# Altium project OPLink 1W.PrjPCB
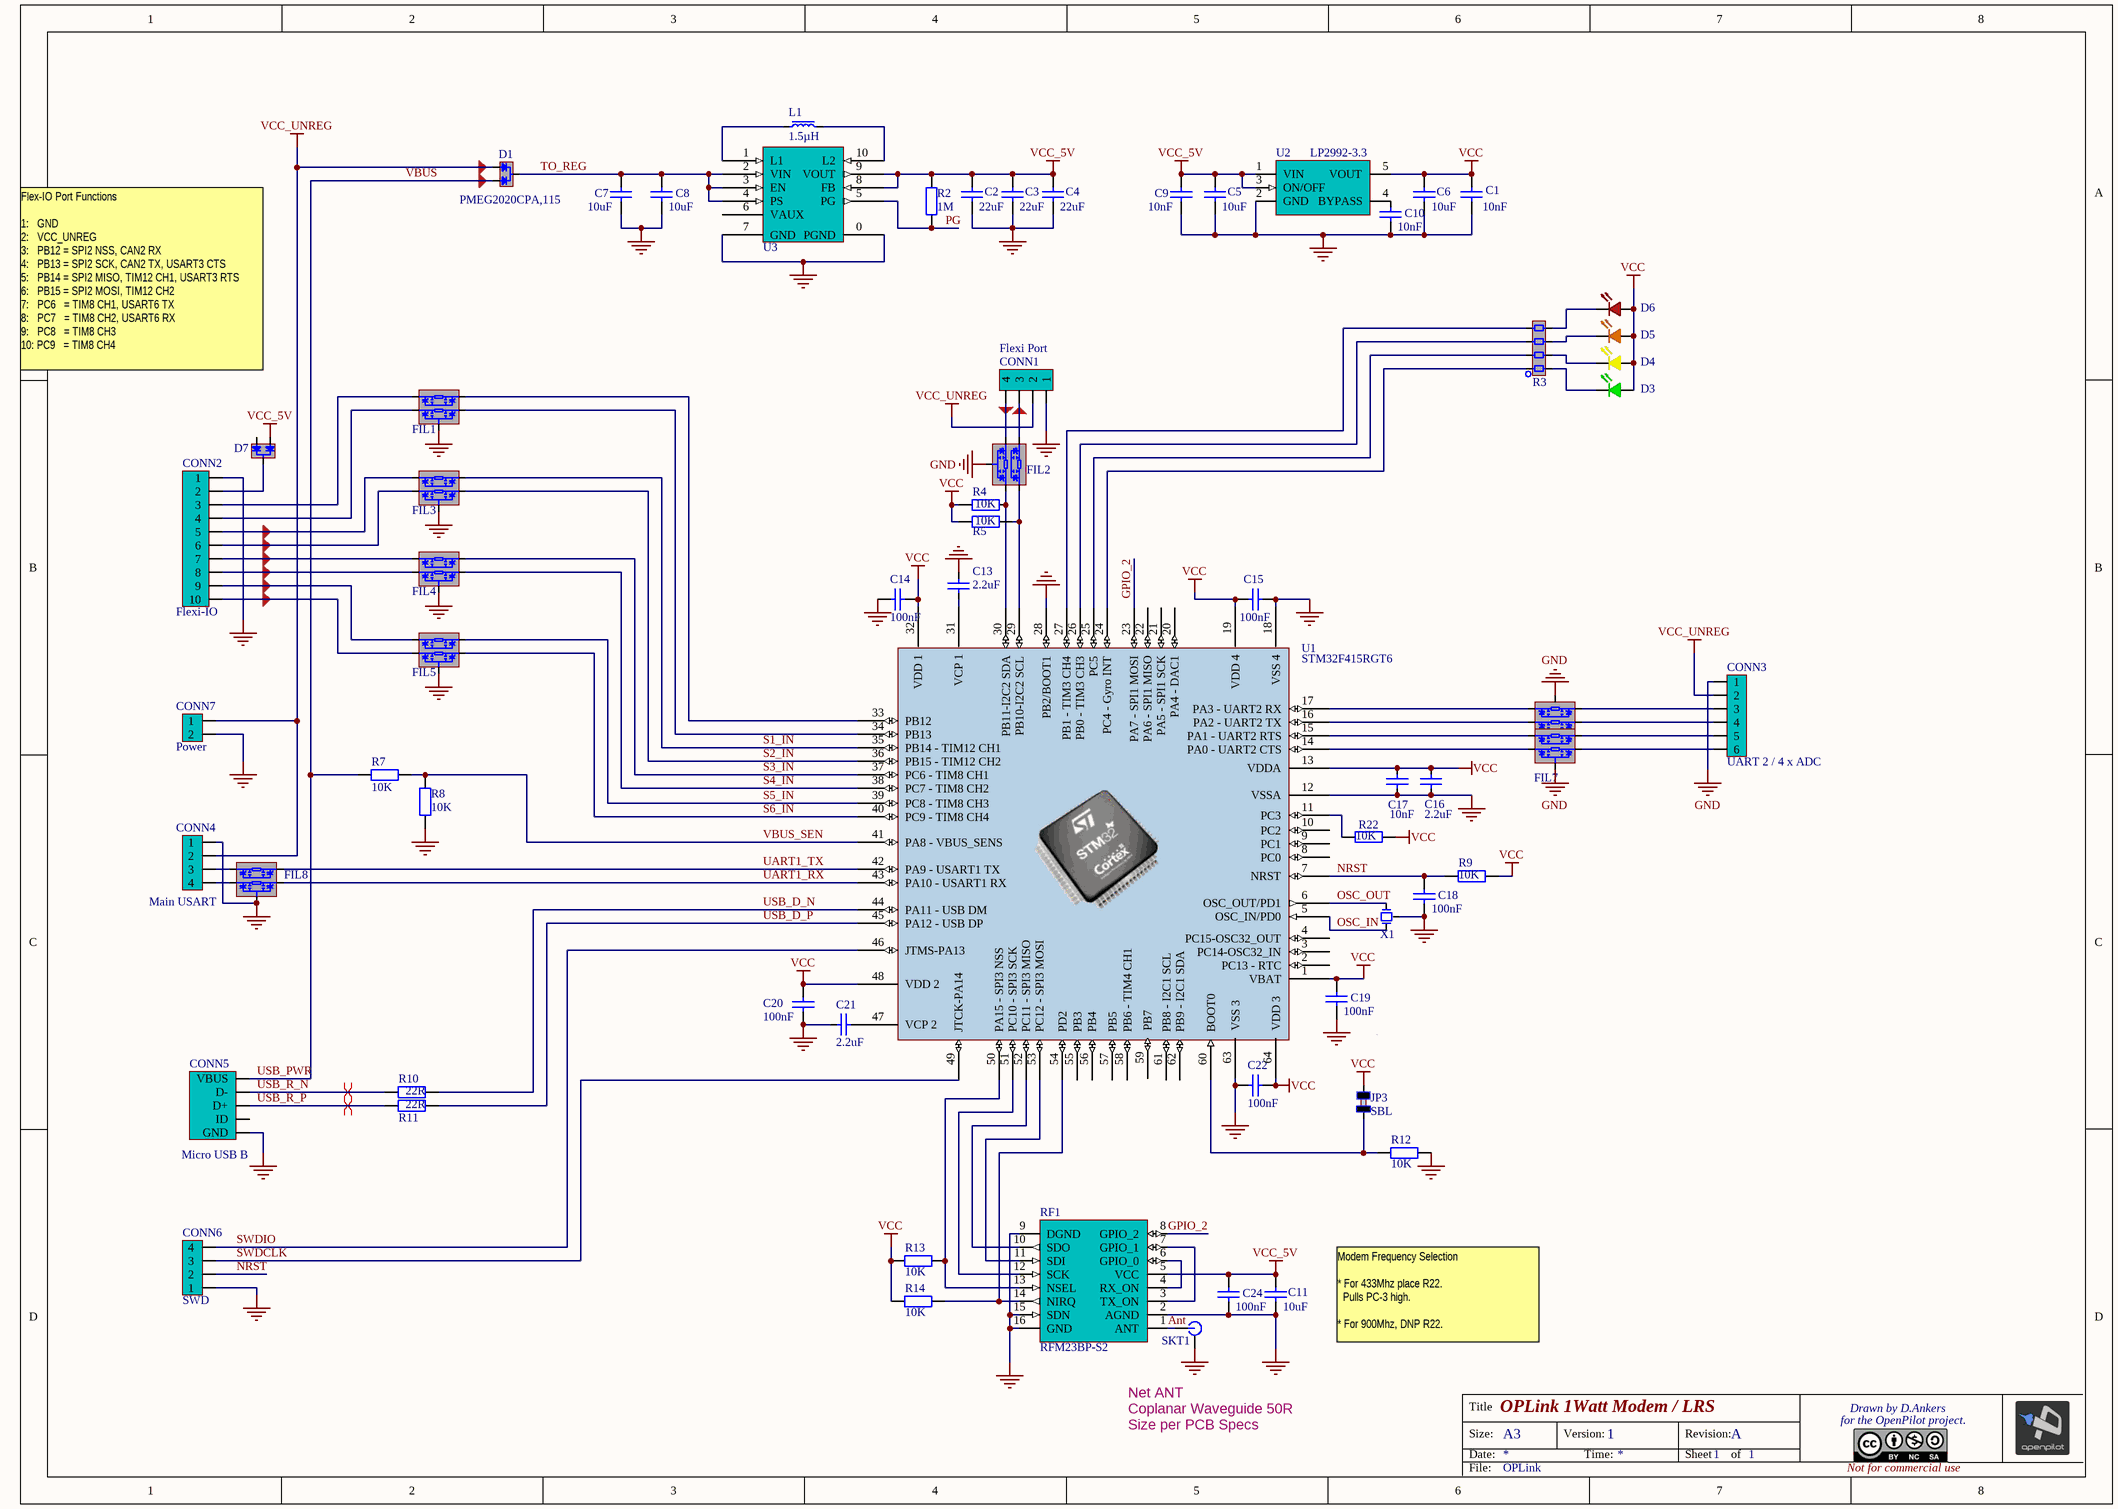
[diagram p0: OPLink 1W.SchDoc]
1 sheet, 64 parts. Net scope: global (net labels, ports and power ports of the same name join across sheets).
Board file: OPLink 1W.PcbDoc

## Sheet OPLink 1W.SchDoc: OPLink 1Watt Modem / LRS
size A3; Author: D. Ankers; CompanyName: The OpenPilot Project; DrawnBy: D. Ankers; Engineer: D. Ankers; Organization: The OpenPilot Project; DocumentNumber: 1; Revision: A; SheetNumber: 1; SheetTotal: 1

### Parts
C1  value 10nF  [CAP402N]  (hidden comment: 10n)
C2  value 22uF  [CAP805L]  (hidden comment: Cap805)
C3  value 22uF  [CAP805L]  (hidden comment: Cap805)
C4  value 22uF  [CAP805L]  (hidden comment: Cap805)
C5  value 10uF  [CAP805L]  (hidden comment: Cap805)
C6  value 10uF  [CAP805L]  (hidden comment: Cap805)
C7  value 10uF  [CAP805L]  (hidden comment: Cap805)
C8  value 10uF  [CAP805L]  (hidden comment: Cap805)
C9  value 10nF  [CAP402N]  (hidden comment: 10n)
C10  value 10nF  [CAP402N]  (hidden comment: 10n)
C11  value 10uF  [CAP805L]  (hidden comment: Cap805)
C13  value 2.2uF  [CAP603L]  (hidden comment: Cap603)
C14  value 100nF  [CAP402N]  (hidden comment: Cap402)
C15  value 100nF  [CAP402N]  (hidden comment: Cap402)
C16  value 2.2uF  [CAP603L]  (hidden comment: Cap603)
C17  value 10nF  (hidden comment: 10n)
C18  value 100nF  [CAP402N]  (hidden comment: Cap402)
C19  value 100nF  [CAP402N]  (hidden comment: Cap402)
C20  value 100nF  [CAP402N]  (hidden comment: Cap402)
C21  value 2.2uF  [CAP603L]  (hidden comment: Cap603)
C22  value 100nF  [CAP402N]  (hidden comment: Cap402)
C24  value 100nF  [CAP402N]  (hidden comment: Cap402)
CONN1  Flexi Port  [JST SH 4 Pin Side Entry]
CONN2  Flexi-IO  [JST SH 10 PIN SIDE ENTRY]
CONN3  UART 2 / 4 x ADC  [JST SH 6 Pin Side Entry]
CONN4  Main USART  [JST SH 4 Pin Side Entry]
CONN5  Micro USB B  [Micro_USB]
CONN6  SWD  [JST SH 4 Pin Side Entry]
CONN7  Power  [JST ZH 2 PIN TOP ENTRY]
D1  PMEG2020CPA,115  [3-HUSON]
D3  Green  [LED603N]  (value not drawn)
D4  Yellow  [LED603N]  (value not drawn)
D5  Orange  [LED603N]  (value not drawn)
D6  Red  [LED603N]  (value not drawn)
D7  PMEG2020CPA,115  [3-HUSON]  (value not drawn)
FIL1  IP4256CZ5-W,115  [SOT-665]  (value not drawn)
FIL2  IP4256CZ5-W,115  [SOT-665]  (value not drawn)
FIL3  IP4256CZ5-W,115  [SOT-665]  (value not drawn)
FIL4  IP4256CZ5-W,115  [SOT-665]  (value not drawn)
FIL5  IP4256CZ5-W,115  [SOT-665]  (value not drawn)
FIL6  IP4256CZ5-W,115  [SOT-665]  (value not drawn)
FIL7  IP4256CZ5-W,115  [SOT-665]  (value not drawn)
FIL8  IP4256CZ5-W,115  [SOT-665]  (value not drawn)
JP3  SBL  [TOUCH JMP 2PAD]
L1  1.5µH  [IND-ASPI-3012S]
R2  value 1M  [RES402N]  (hidden comment: Res402)
R3  Res Array 330R 1206  [TC164]  (value not drawn)
R4  value 10K  [RES402N]  (hidden comment: Res402)
R5  value 10K  [RES402N]  (hidden comment: Res402)
R7  value 10K  [RES402N]  (hidden comment: Res402)
R8  value 10K  [RES402N]  (hidden comment: Res402)
R9  value 10K  [RES402N]  (hidden comment: Res402)
R10  value 22R  [RES402N]  (hidden comment: Res402)
R11  value 22R  [RES402N]  (hidden comment: Res402)
R12  value 10K  [RES402N]  (hidden comment: Res402)
R13  value 10K  [RES402N]  (hidden comment: Res402)
R14  value 10K  [RES402N]  (hidden comment: Res402)
R22  value 10K  [RES402N]  (hidden comment: Res402)
RF1  RFM23BP-S2  [RFM23BP-S2]
SKT1  MMCX Thru hole  [MMCX_SOCKET]  (value not drawn)
U1  STM32F415RGT6  [STM32 64 Lead]
U2  LP2992-3.3  [SOT23-5L]
U3  TPS63061  [SON-10]  (value not drawn)
X1  8Mhz Ceralock  [CERALOCK 8Mhz]  (value not drawn)

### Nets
GND: C1.2 C2.2 C3.2 C4.2 C5.2 C6.2 C7.2 C8.2 C9.2 C10.2 C11.2 C13.1 C14.2 C15.1 C16.1 C17.2 C18.1 C19.1 C20.2 C21.1 C22.2 C24.1 CONN1.1 CONN2.1 CONN3.1 CONN4.1 CONN5.5(GND) CONN6.1 CONN7.2 FIL1.2(PAD) FIL2.2(PAD) FIL3.2(PAD) FIL4.2(PAD) FIL5.2(PAD) FIL6.2(PAD) FIL7.2(PAD) FIL8.2(PAD) R8.1 R12.2 RF1.2(AGND) RF1.9(N.C) RF1.15(SDN) RF1.16(GND) SKT1.2(GND) U1.12(VSSA) U1.18(VSS_4) U1.28(PB2/BOOT1) U1.63(VSS_3) U2.2(GND) U3.0(PGND) U3.7(GND) X1.3
VCC: C1.1 C6.1 C14.1 C15.2 C16.2 C17.1 C19.2 C20.1 C22.1 D3.2(A) D4.2(A) D5.2(A) D6.2(A) JP3.2 R4.2 R5.2 R9.2 R13.2 R14.2 R22.1 U1.1(VBAT) U1.13(VDDA) U1.19(VDD_4) U1.32(VDD_1) U1.48(VDD_2) U1.64(VDD_3) U2.5(VOUT)
VCC_5V: C2.1 C3.1 C4.1 C5.1 C9.1 C11.1 C24.2 D7.2(A2) R2.1 RF1.5(VCC) U2.1(VIN) U2.3(ON/OFF) U3.8(FB) U3.9(VOUT)
VCC_UNREG: CONN1.2 CONN3.2 CONN4.2 CONN7.1 D1.1(A1)
Ant: RF1.1(N.C) SKT1.1(PIN)
GPIO_2: RF1.8(N.C) U1.23(PA7_-_SPI1_MOSI)
NRST: C18.2 CONN6.2 R9.1 U1.7(NRST)
OSC_IN: U1.5(OSC_IN/PD0) X1.1
OSC_OUT: U1.6(OSC_OUT/PD1) X1.2
PG: R2.2 U3.5(PG)
S1_IN: FIL3.3 U1.35(PB14_-_TIM12_CH1)
S2_IN: FIL3.1 U1.36(PB15_-_TIM12_CH2)
S3_IN: FIL4.3 U1.37(PC6_-_TIM8_CH1)
S4_IN: FIL4.1 U1.38(PC7_-_TIM8_CH2)
S5_IN: FIL5.3 U1.39(PC8_-_TIM8_CH3)
S6_IN: FIL5.1 U1.40(PC9_-_TIM8_CH4)
SWDCLK: CONN6.3 U1.49(JTCK-PA14)
SWDIO: CONN6.4 U1.46(JTMS-PA13)
TO_REG: C7.1 C8.1 D1.3(COM) U3.2(VIN) U3.3(EN) U3.4(PS)
UART1_RX: FIL8.1 U1.43(PA10_-_USART1_RX)
UART1_TX: FIL8.3 U1.42(PA9_-_USART1_TX)
USB_D_N: R10.1 U1.44(PA11_-_USB_DM)
USB_D_P: R11.1 U1.45(PA12_-_USB_DP)
USB_PWR: CONN5.1(VBUS) D1.2(A2) R7.1  [also labelled VBUS]
USB_R_N: CONN5.2(D-) R10.2
USB_R_P: CONN5.3(D+) R11.2
VBUS_SEN: R7.2 R8.2 U1.41(PA8_-_VBUS_SENS)
NetC10_1: C10.1 U2.4(BYPASS)
NetC13_2: C13.2 U1.31(VCP_1)
NetC21_2: C21.2 U1.47(VCP_2)
NetCONN1_3: CONN1.3 FIL2.4
NetCONN1_4: CONN1.4 FIL2.5
NetCONN2_2: CONN2.2 D7.3(COM)
NetCONN2_3: CONN2.3 FIL1.4
NetCONN2_4: CONN2.4 FIL1.5
NetCONN2_5: CONN2.5 FIL3.4
NetCONN2_6: CONN2.6 FIL3.5
NetCONN2_7: CONN2.7 FIL4.4
NetCONN2_8: CONN2.8 FIL4.5
NetCONN2_9: CONN2.9 FIL5.4
NetCONN2_10: CONN2.10 FIL5.5
NetCONN3_3: CONN3.3 FIL6.4
NetCONN3_4: CONN3.4 FIL6.5
NetCONN3_5: CONN3.5 FIL7.4
NetCONN3_6: CONN3.6 FIL7.5
NetCONN4_3: CONN4.3 FIL8.4
NetCONN4_4: CONN4.4 FIL8.5
NetD3_1: D3.1(K) R3.5
NetD4_1: D4.1(K) R3.6
NetD5_1: D5.1(K) R3.7
NetD6_1: D6.1(K) R3.8
NetFIL1_1: FIL1.1 U1.34(PB13)
NetFIL1_3: FIL1.3 U1.33(PB12)
NetFIL2_1: FIL2.1 R4.1 U1.30(PB11-I2C2_SDA)
NetFIL2_3: FIL2.3 R5.1 U1.29(PB10-I2C2_SCL)
NetFIL6_1: FIL6.1 U1.16(PA2_-_UART2_TX)
NetFIL6_3: FIL6.3 U1.17(PA3_-_UART2_RX)
NetFIL7_1: FIL7.1 U1.14(PA0_-_UART2_CTS)
NetFIL7_3: FIL7.3 U1.15(PA1_-_UART2_RTS)
NetJP3_1: JP3.1 R12.1 U1.60(BOOT0)
NetL1_1: L1.1 U3.1(L1)
NetL1_2: L1.2 U3.10(L2)
NetR3_1: R3.1 U1.27(PB1_-_TIM3_CH4)
NetR3_2: R3.2 U1.26(PB0_-_TIM3_CH3)
NetR3_3: R3.3 U1.25(PC5)
NetR3_4: R3.4 U1.24(PC4_-_Gyro_INT)
NetR13_1: R13.1 RF1.13(NSEL) U1.50(PA15_-_SPI3_NSS)
NetR14_1: R14.1 RF1.14(N.C) U1.54(PD2)
NetR22_2: R22.2 U1.11(PC3)
NetRF1_3: RF1.3(TX_ON) RF1.7(GPIO_1)
NetRF1_4: RF1.4(N.C) RF1.6(GPIO_0)
NetRF1_10: RF1.10(SDO) U1.52(PC11_-_SPI3_MISO)
NetRF1_11: RF1.11(SDI) U1.53(PC12_-_SPI3_MOSI)
NetRF1_12: RF1.12(SCK) U1.51(PC10_-_SPI3_SCK)

Not connected (* = marked no-connect by the designer): CONN5 0(SCN) 4(ID); D7 1(A1); U1 2(PC13_-_RTC) 3(PC14-OSC32_IN) 4(PC15-OSC32_OUT) 8(PC0) 9(PC1) 10(PC2) 20(PA4_-_DAC1) 21(PA5_-_SPI1_SCK) 22(PA6_-_SPI1_MISO) 55(PB3) 56(PB4) 57(PB5) 58(PB6_-_TIM4_CH1) 59(PB7) 61(PB8_-_I2C1_SCL) 62(PB9_-_I2C1_SDA); U3 6(VAUX)

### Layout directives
differential pair: USB_R_N, USB_R_P

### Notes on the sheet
- Flex-IO Port Functions
  1:   GND
  2:   VCC_UNREG
  3:   PB12 = SPI2 NSS, CAN2 RX
  4:   PB13 = SPI2 SCK, CAN2 TX, USART3 CTS
  5:   PB14 = SPI2 MISO, TIM12 CH1, USART3 RTS
  6:   PB15 = SPI2 MOSI, TIM12 CH2
  7:   PC6   = TIM8 CH1, USART6 TX
  8:   PC7   = TIM8 CH2, USART6 RX
  9:   PC8   = TIM8 CH3
  10: PC9   = TIM8 CH4
- Modem Frequency Selection
  * For 433Mhz place R22.
  Pulls PC-3 high.
  * For 900Mhz, DNP R22.
- Net ANT
  Coplanar Waveguide 50R
  Size per PCB Specs
- Title
- Size:
- Date:
- A3
- Version:
- Time:
- Revision:
- Sheet
- of
- for the OpenPilot project.
- Drawn by D.Ankers
- File:
- Not for commercial use

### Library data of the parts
C1 C9 C10 C14 C15 C17-C20 C22 C24 = Cap402: Capacitor SMD
C2-C8 C11 = Cap805: Capacitor SMD
C13 C16 C21 = Cap603: Capacitor SMD
CONN1 CONN4 CONN6 = JST-SH 4-pin Side Entry Socket: Manufacturer: Generic Components; Class: Connector
CONN2 = JST-SH 10-pin Side Entry Socket: Manufacturer: Generic Components; Class: Connector
CONN3 = JST-SH 6-pin Side Entry Socket: Manufacturer: Generic Components; Class: Connector
CONN5 = USB Micro B SMT: USB Micro B SMT Socket; Class: Connector
CONN7 = JST ZH 2-pin Top Entry Socket: JST ZH 1.5mm 2-pin TopEntry Socket; Manufacturer: Generic Components; Class: Connector
D1 D7 = PMEG2020CPA,115: Dual Diode Command Cathode 2A
D3 = LED 603 Gr: Green 603 LED; Value: 2.1v 20mA
D4 = LED 603 Yellow: Yellow 603 LED; Value: 2.1v 20mA
D5 = LED 603 Or: Orange 603 LED; Value: 2.1v 20mA
D6 = LED 603 Red: Red 603 LED; Value: 2.1v 20mA
FIL1-FIL8 = RF Filter 100R 30pF: IP4256CZ5-W,115 2 channel, 100R, 30pF, RF ESD Filter; Manufacturer: Generic Components; Class: Passive
JP3 = 2 PAD Touch JMP: 2 Pad Touch Jumper
L1 = Pwr Inductor 1.5µH: Power Inductor 1.5µH; Manufacturer: Generic Components; Class: Passive
R2 R4 R5 R7-R14 R22 = Res402: Resistor SMD
R3 = Res Array 330R: 4 Resistor Array; Class: Passive
RF1 = RFM23BP-S2: UHF 1W Transceiver
SKT1 = MMCX Thru hole: MMCX Socket
U1 = STM32F103RET6: STM32 ARM-based 32-bit MCU with 1MB Flash, 64-pin LQFP, Industrial Temperature
U2 = LP2992-3.3: 3.3V 250mA LDO Regulator
X1 = CERALOCK8: Ceralock 8Mhz with caps; Class: Oscillator; SubClass: Ceramic Oscillator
